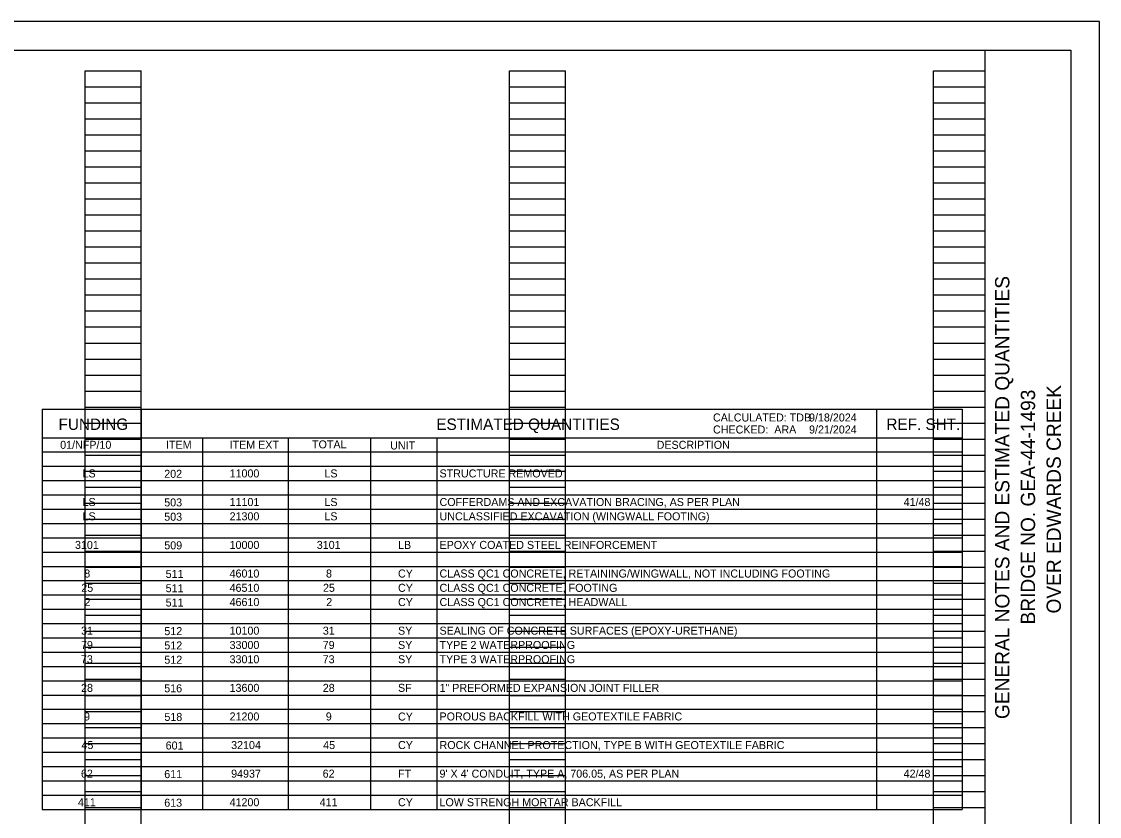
# Model space of a CAD drawing. Extents: x 0 to 36.2, y 0 to 22.
# Drawn here: x 15.15 to 34, y 8.1 to 22 of the extents above; entities that cross this region are included whole.
import ezdxf

# ---------------------------------------------------------------- set-up
doc = ezdxf.new("R2010")
doc.units = 0
for name, color, linetype in [('SC_Scratch1', 7, 'Continuous'), ('SH_Border', 7, 'Continuous'), ('SH_Cut_Line', 7, 'Continuous'), ('SH_Data', 7, 'Continuous'), ('ST_Details', 7, 'Continuous'), ('ST_Text', 7, 'Continuous')]:
    doc.layers.add(name, color=color, linetype=linetype)

msp = doc.modelspace()

# ---------------------------------------------------------------- linework, layer by layer
at = {"layer": 'SC_Scratch1'}
for p, q in [((16.26, 0.98), (16.26, 21.14)), ((16.26, 21.14), (17.24, 21.14)), ((17.24, 0.98), (17.24, 21.14)), ((23.68, 0.98), (23.68, 21.14)), ((23.68, 21.14), (24.66, 21.14)), ((24.66, 0.98), (24.66, 21.14)), ((31.1, 0.98), (31.1, 21.14)), ((31.1, 21.14), (32, 21.14)), ((32, 0.98), (32, 21.14)), ((16.26, 20.86), (17.24, 20.86)), ((23.68, 20.86), (24.66, 20.86)), ((31.1, 20.86), (32, 20.86)), ((16.26, 20.58), (17.24, 20.58)), ((23.68, 20.58), (24.66, 20.58)), ((31.1, 20.58), (32, 20.58)), ((16.26, 20.3), (17.24, 20.3)), ((23.68, 20.3), (24.66, 20.3)), ((31.1, 20.3), (32, 20.3)), ((16.26, 20.02), (17.24, 20.02)), ((23.68, 20.02), (24.66, 20.02)), ((31.1, 20.02), (32, 20.02)), ((16.26, 19.74), (17.24, 19.74)), ((23.68, 19.74), (24.66, 19.74)), ((31.1, 19.74), (32, 19.74)), ((16.26, 19.46), (17.24, 19.46)), ((23.68, 19.46), (24.66, 19.46)), ((31.1, 19.46), (32, 19.46)), ((16.26, 19.18), (17.24, 19.18)), ((23.68, 19.18), (24.66, 19.18)), ((31.1, 19.18), (32, 19.18)), ((16.26, 18.9), (17.24, 18.9)), ((23.68, 18.9), (24.66, 18.9)), ((31.1, 18.9), (32, 18.9)), ((16.26, 18.62), (17.24, 18.62)), ((23.68, 18.62), (24.66, 18.62)), ((31.1, 18.62), (32, 18.62)), ((16.26, 18.34), (17.24, 18.34)), ((23.68, 18.34), (24.66, 18.34)), ((31.1, 18.34), (32, 18.34)), ((16.26, 18.06), (17.24, 18.06)), ((23.68, 18.06), (24.66, 18.06)), ((31.1, 18.06), (32, 18.06)), ((16.26, 17.78), (17.24, 17.78)), ((23.68, 17.78), (24.66, 17.78)), ((31.1, 17.78), (32, 17.78)), ((16.26, 17.5), (17.24, 17.5)), ((23.68, 17.5), (24.66, 17.5)), ((31.1, 17.5), (32, 17.5)), ((16.26, 17.22), (17.24, 17.22)), ((23.68, 17.22), (24.66, 17.22)), ((31.1, 17.22), (32, 17.22)), ((16.26, 16.94), (17.24, 16.94)), ((23.68, 16.94), (24.66, 16.94)), ((31.1, 16.94), (32, 16.94)), ((16.26, 16.66), (17.24, 16.66)), ((23.68, 16.66), (24.66, 16.66)), ((31.1, 16.66), (32, 16.66)), ((16.26, 16.38), (17.24, 16.38)), ((23.68, 16.38), (24.66, 16.38)), ((31.1, 16.38), (32, 16.38)), ((16.26, 16.1), (17.24, 16.1)), ((23.68, 16.1), (24.66, 16.1)), ((31.1, 16.1), (32, 16.1)), ((16.26, 15.82), (17.24, 15.82)), ((23.68, 15.82), (24.66, 15.82)), ((31.1, 15.82), (32, 15.82)), ((16.26, 15.54), (17.24, 15.54)), ((23.68, 15.54), (24.66, 15.54)), ((31.1, 15.54), (32, 15.54)), ((16.26, 15.26), (17.24, 15.26)), ((23.68, 15.26), (24.66, 15.26)), ((31.1, 15.26), (32, 15.26)), ((16.26, 14.98), (17.24, 14.98)), ((23.68, 14.98), (24.66, 14.98)), ((31.1, 14.98), (32, 14.98)), ((16.26, 14.7), (17.24, 14.7)), ((23.68, 14.7), (24.66, 14.7)), ((31.1, 14.7), (32, 14.7)), ((16.26, 14.42), (17.24, 14.42)), ((23.68, 14.42), (24.66, 14.42)), ((31.1, 14.42), (32, 14.42)), ((16.26, 14.14), (17.24, 14.14)), ((23.68, 14.14), (24.66, 14.14)), ((31.1, 14.14), (32, 14.14)), ((16.26, 13.86), (17.24, 13.86)), ((23.68, 13.86), (24.66, 13.86)), ((31.1, 13.86), (32, 13.86)), ((16.26, 13.58), (17.24, 13.58)), ((23.68, 13.58), (24.66, 13.58)), ((31.1, 13.58), (32, 13.58)), ((16.26, 13.3), (17.24, 13.3)), ((23.68, 13.3), (24.66, 13.3)), ((31.1, 13.3), (32, 13.3)), ((16.26, 13.02), (17.24, 13.02)), ((23.68, 13.02), (24.66, 13.02)), ((31.1, 13.02), (32, 13.02)), ((16.26, 12.74), (17.24, 12.74)), ((23.68, 12.74), (24.66, 12.74)), ((31.1, 12.74), (32, 12.74)), ((16.26, 12.46), (17.24, 12.46)), ((23.68, 12.46), (24.66, 12.46)), ((31.1, 12.46), (32, 12.46)), ((16.26, 12.18), (17.24, 12.18)), ((23.68, 12.18), (24.66, 12.18)), ((31.1, 12.18), (32, 12.18)), ((16.26, 11.9), (17.24, 11.9)), ((23.68, 11.9), (24.66, 11.9)), ((31.1, 11.9), (32, 11.9)), ((16.26, 11.62), (17.24, 11.62)), ((23.68, 11.62), (24.66, 11.62)), ((31.1, 11.62), (32, 11.62)), ((16.26, 11.34), (17.24, 11.34)), ((23.68, 11.34), (24.66, 11.34)), ((31.1, 11.34), (32, 11.34)), ((16.26, 11.06), (17.24, 11.06)), ((23.68, 11.06), (24.66, 11.06)), ((31.1, 11.06), (32, 11.06)), ((16.26, 10.78), (17.24, 10.78)), ((23.68, 10.78), (24.66, 10.78)), ((31.1, 10.78), (32, 10.78)), ((16.26, 10.5), (17.24, 10.5)), ((23.68, 10.5), (24.66, 10.5)), ((31.1, 10.5), (32, 10.5)), ((16.26, 10.22), (17.24, 10.22)), ((23.68, 10.22), (24.66, 10.22)), ((31.1, 10.22), (32, 10.22)), ((16.26, 9.94), (17.24, 9.94)), ((23.68, 9.94), (24.66, 9.94)), ((31.1, 9.94), (32, 9.94)), ((16.26, 9.66), (17.24, 9.66)), ((23.68, 9.66), (24.66, 9.66)), ((31.1, 9.66), (32, 9.66)), ((16.26, 9.38), (17.24, 9.38)), ((23.68, 9.38), (24.66, 9.38)), ((31.1, 9.38), (32, 9.38)), ((16.26, 9.1), (17.24, 9.1)), ((23.68, 9.1), (24.66, 9.1)), ((31.1, 9.1), (32, 9.1)), ((16.26, 8.82), (17.24, 8.82)), ((23.68, 8.82), (24.66, 8.82)), ((31.1, 8.82), (32, 8.82)), ((16.26, 8.54), (17.24, 8.54)), ((23.68, 8.54), (24.66, 8.54)), ((31.1, 8.54), (32, 8.54)), ((16.26, 8.26), (17.24, 8.26)), ((23.68, 8.26), (24.66, 8.26)), ((31.1, 8.26), (32, 8.26))]:
    msp.add_line(p, q, dxfattribs=at)
at = {"layer": 'SH_Border'}
msp.add_line((32, 0.5), (32, 21.5), dxfattribs=at)
msp.add_lwpolyline([(1.5, 21.5), (33.5, 21.5), (33.5, 0.5), (1.5, 0.5)], close=True, dxfattribs=at)
at = {"layer": 'SH_Cut_Line'}
msp.add_lwpolyline([(0, 0), (34, 0), (34, 22), (0, 22)], close=True, dxfattribs=at)
at = {"layer": 'ST_Details'}
for p, q in [((15.51, 15.225), (31.6, 15.225)), ((15.51, 15.225), (15.51, 8.226)), ((17.24, 15.225), (17.24, 8.226)), ((30.102, 15.225), (30.102, 8.226)), ((31.6, 15.225), (31.6, 8.226)), ((15.51, 14.725), (31.6, 14.725)), ((18.312, 14.725), (18.312, 8.226)), ((19.811, 14.725), (19.811, 8.226)), ((21.252, 14.725), (21.252, 8.226)), ((22.409, 14.725), (22.409, 8.226)), ((15.51, 14.475), (31.6, 14.475)), ((15.51, 14.225), (31.6, 14.225)), ((15.51, 13.975), (31.6, 13.975)), ((15.51, 13.725), (31.6, 13.725)), ((15.51, 13.475), (31.6, 13.475)), ((15.51, 13.225), (31.6, 13.225)), ((15.51, 12.975), (31.6, 12.975)), ((15.51, 12.725), (31.6, 12.725)), ((15.51, 12.475), (31.6, 12.475)), ((15.51, 12.225), (31.6, 12.225)), ((15.51, 11.976), (31.6, 11.976)), ((15.51, 11.726), (31.6, 11.726)), ((15.51, 11.476), (31.6, 11.476)), ((15.51, 11.226), (31.6, 11.226)), ((15.51, 10.976), (31.6, 10.976)), ((15.51, 10.726), (31.6, 10.726)), ((15.51, 10.476), (31.6, 10.476)), ((15.51, 10.226), (31.6, 10.226)), ((15.51, 9.976), (31.6, 9.976)), ((15.51, 9.726), (31.6, 9.726)), ((29.948, 9.726), (29.948, 9.726)), ((15.51, 9.476), (31.6, 9.476)), ((15.51, 9.226), (31.6, 9.226)), ((15.51, 8.976), (31.6, 8.976)), ((15.51, 8.726), (31.6, 8.726)), ((15.51, 8.476), (31.6, 8.476)), ((15.51, 8.226), (31.6, 8.226))]:
    msp.add_line(p, q, dxfattribs=at)

# ---------------------------------------------------------------- texts
at = {"layer": 'SH_Data'}
for s, p in [('GENERAL NOTES AND ESTIMATED QUANTITIES', (32.425, 9.806)), ('BRIDGE NO. GEA-44-1493', (32.875, 11.459)), ('OVER EDWARDS CREEK', (33.325, 11.651))]:
    msp.add_text(s, height=0.25, rotation=90, dxfattribs=at).set_placement(p)
at = {"layer": 'ST_Text'}
for s, height, p in [('CALCULATED: TDB', 0.14, (27.241, 15.008)), ('9/18/2024', 0.14, (28.921, 15.008)), ('FUNDING', 0.2, (15.795, 14.86)), ('ESTIMATED QUANTITIES', 0.2, (22.402, 14.86)), ('CHECKED:  ARA', 0.14, (27.241, 14.798)), ('9/21/2024', 0.14, (28.921, 14.798)), ('REF. SHT.', 0.2, (30.274, 14.86)), ('01/NFP/10', 0.14, (15.823, 14.53)), ('ITEM', 0.14, (17.675, 14.53)), ('ITEM EXT', 0.14, (18.786, 14.53)), ('TOTAL', 0.14, (20.228, 14.538)), ('UNIT', 0.14, (21.595, 14.519)), ('DESCRIPTION', 0.14, (26.256, 14.53)), ('LS', 0.14, (16.215, 14.03)), ('202', 0.14, (17.643, 14.023)), ('11000', 0.14, (18.786, 14.03)), ('LS', 0.14, (20.444, 14.03)), ('STRUCTURE REMOVED', 0.14, (22.458, 14.03)), ('LS', 0.14, (16.215, 13.53)), ('503', 0.14, (17.643, 13.523)), ('11101', 0.14, (18.786, 13.53)), ('LS', 0.14, (20.444, 13.53)), ('COFFERDAMS AND EXCAVATION BRACING, AS PER PLAN', 0.14, (22.458, 13.53)), ('41/48', 0.14, (30.575, 13.53)), ('LS', 0.14, (16.215, 13.28)), ('503', 0.14, (17.643, 13.273)), ('21300', 0.14, (18.786, 13.28)), ('LS', 0.14, (20.444, 13.28)), ('UNCLASSIFIED EXCAVATION (WINGWALL FOOTING)', 0.14, (22.458, 13.28)), ('3101', 0.14, (16.082, 12.78)), ('509', 0.14, (17.644, 12.773)), ('10000', 0.14, (18.786, 12.78)), ('3101', 0.14, (20.311, 12.78)), ('LB', 0.14, (21.732, 12.78)), ('EPOXY COATED STEEL REINFORCEMENT', 0.14, (22.458, 12.78)), ('8', 0.14, (16.244, 12.28)), ('511', 0.14, (17.668, 12.273)), ('46010', 0.14, (18.786, 12.28)), ('8', 0.14, (20.472, 12.28)), ('CY', 0.14, (21.732, 12.28)), ('CLASS QC1 CONCRETE, RETAINING/WINGWALL, NOT INCLUDING FOOTING', 0.14, (22.458, 12.28)), ('25', 0.14, (16.192, 12.03)), ('511', 0.14, (17.668, 12.023)), ('46510', 0.14, (18.786, 12.03)), ('25', 0.14, (20.42, 12.03)), ('CY', 0.14, (21.732, 12.03)), ('CLASS QC1 CONCRETE, FOOTING', 0.14, (22.458, 12.03)), ('2', 0.14, (16.249, 11.781)), ('511', 0.14, (17.668, 11.773)), ('46610', 0.14, (18.786, 11.781)), ('2', 0.14, (20.477, 11.781)), ('CY', 0.14, (21.732, 11.781)), ('CLASS QC1 CONCRETE, HEADWALL', 0.14, (22.458, 11.781)), ('31', 0.14, (16.188, 11.281)), ('512', 0.14, (17.645, 11.273)), ('10100', 0.14, (18.786, 11.281)), ('31', 0.14, (20.417, 11.281)), ('SY', 0.14, (21.732, 11.281)), ('SEALING OF CONCRETE SURFACES (EPOXY-URETHANE)', 0.14, (22.458, 11.281)), ('79', 0.14, (16.187, 11.031)), ('512', 0.14, (17.645, 11.023)), ('33000', 0.14, (18.786, 11.031)), ('79', 0.14, (20.415, 11.031)), ('SY', 0.14, (21.732, 11.031)), ('TYPE 2 WATERPROOFING', 0.14, (22.458, 11.031)), ('73', 0.14, (16.186, 10.781)), ('512', 0.14, (17.645, 10.773)), ('33010', 0.14, (18.786, 10.781)), ('73', 0.14, (20.414, 10.781)), ('SY', 0.14, (21.732, 10.781)), ('TYPE 3 WATERPROOFING', 0.14, (22.458, 10.781)), ('28', 0.14, (16.188, 10.281)), ('516', 0.14, (17.643, 10.273)), ('13600', 0.14, (18.786, 10.281)), ('28', 0.14, (20.416, 10.281)), ('SF', 0.14, (21.732, 10.281)), ('1" PREFORMED EXPANSION JOINT FILLER', 0.14, (22.458, 10.281)), ('9', 0.14, (16.24, 9.781)), ('518', 0.14, (17.646, 9.773)), ('21200', 0.14, (18.786, 9.781)), ('9', 0.14, (20.469, 9.781)), ('CY', 0.14, (21.732, 9.779)), ('POROUS BACKFILL WITH GEOTEXTILE FABRIC', 0.14, (22.458, 9.781)), ('45', 0.14, (16.195, 9.281)), ('601', 0.14, (17.668, 9.273)), ('32104', 0.14, (18.813, 9.281)), ('45', 0.14, (20.423, 9.281)), ('CY', 0.14, (21.732, 9.281)), ('ROCK CHANNEL PROTECTION, TYPE B WITH GEOTEXTILE FABRIC', 0.14, (22.458, 9.281)), ('62', 0.14, (16.186, 8.781)), ('611', 0.14, (17.643, 8.773)), ('94937', 0.14, (18.813, 8.781)), ('62', 0.14, (20.414, 8.781)), ('FT', 0.14, (21.732, 8.781)), ("9' X 4' CONDUIT, TYPE A, 706.05, AS PER PLAN", 0.14, (22.458, 8.781)), ('42/48', 0.14, (30.575, 8.781)), ('411', 0.14, (16.133, 8.281)), ('613', 0.14, (17.643, 8.273)), ('41200', 0.14, (18.786, 8.281)), ('411', 0.14, (20.361, 8.281)), ('CY', 0.14, (21.732, 8.281)), ('LOW STRENGH MORTAR BACKFILL', 0.14, (22.458, 8.281))]:
    msp.add_text(s, height=height, dxfattribs=at).set_placement(p)

doc.saveas('drawing.dxf')
